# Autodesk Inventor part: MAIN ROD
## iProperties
Shininess: 64.0
Length Units: 11269
Angle Units: 11279
Time Units: 11290
Mass Units: 11283
Length Display Precision: 3
Angle Display Precision: 2
Compacted: True
Part Number: MAIN ROD
Document SubType Name: Modeling
Created: 2004-05
Designer: Daniel
Manufacturer: Standard
Standards Organization: Custom
Density: 0.0
Volumn: 0.0
Area: 0.0
PropertySet Name: Model Information
Control State: 0
Master: False
Checked Out: False
Author: Daniel
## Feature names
1. Extrusion1
2. Extrusion2
3. Extrusion3
4. Extrusion4
5. Extrusion5
6. Extrusion6
